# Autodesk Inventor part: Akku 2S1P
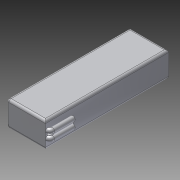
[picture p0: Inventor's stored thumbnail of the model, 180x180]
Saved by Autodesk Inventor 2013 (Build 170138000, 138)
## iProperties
Created: 2012-08
Part Number: Akku 2S1P
Material: LCP-Kunststoff
Document SubType Name: Modeling
Designer: rYan
Mass: 131.468 g
Surface Area: 137.12 cm^2
Volume: 80.8535 cm^3
Density: 1.626 g/cm^3
Author: rYan
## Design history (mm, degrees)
sketch "Skizze1"
  geometry: L1 (-17, 54)-(17, 54); L2 (17, 54)-(17, -54); L3 (17, -54)-(-17, -54); L4 (-17, -54)-(-17, 54); L5 (0, 75.6)-(0, -75.6) reference; L6 (-23.8, 0)-(23.8, 0) reference; 1 further point
  constraints: 8 end point, 2 parallel, 1 horizontal, 1 perpendicular, 2 other
  dimensions: "d0" = 34 distance of L1.start L1.end; "d2" = 108 distance of L1.end L2.end
extrude "Extrusion1" new body sketch "Skizze1" distance "d3" = 22; taper "d4" = 0 deg
fillet "Rundung1" dims "d5" = 2
workplane "Arbeitsebene1"
sketch "Skizze2"
  geometry: L1 (-17, -54)-(-17, 54) reference; L2 (15, -54)-(-17, -54) reference; L3 (-19, -50)-(-17, -50); L4 (-19, -50)-(-19, -32); A1 r 2 centre (-17, -50) between (-19, -50) and (-17, -52); 1 further point
  constraints: 4 end point, 2 perpendicular, 2 point on circle, 2 point on line, 1 centre point, 1 coincident, 1 tangent
  dimensions: "d6" = 2 radius of A1; "d8" = 2 distance from line of A1.end L2; "d11" = 18 distance of L3.start L4.end
sketch "Skizze3"
  geometry: L1 (-9, 129.6)-(-9, -21.6) reference; C1 r 0.75 at (-9, 2); 2 further points
  constraints: 1 centre point, 1 coincident
  dimensions: "d9" = 1.5 diameter of C1
feature "Sweeping1" sketch "Skizze2", "Skizze3" dims "d12" = 0
workplane "Arbeitsebene2"
sketch "Skizze4"
  geometry: L1 (-17, -52.75)-(-17, -51.25) reference; L2 (-17, 54)-(-17, -54) reference; L3 (-17, -54)-(-17, 54) reference; L4 (-17, -54)-(15, -54) reference; L5 (15, -54)-(-17, -54) reference; L6 (-17, -50)-(-19, -50); L7 (-19, -50)-(-19, -32); A1 r 2 centre (-17, -50) between (-19, -50) and (-17, -52); 1 further point
  constraints: 4 end point, 2 point on circle, 2 point on line, 1 centre point, 1 perpendicular, 1 tangent
  dimensions: "d18" = 2 radius of A1; "d20" = 2 distance from line of A1.end L4; "d21" = 90 deg angle of L2 L6; "d22" = 18 distance of L6.end L7.end
sketch "Skizze5"
  geometry: C1 r 2 at (-6, 2); 2 further points
  constraints: 1 centre point, 1 coincident
  dimensions: "d23" = 4 diameter of C1
feature "Sweeping2" sketch "Skizze4", "Skizze5" dims "d25" = 0
mirror "Spiegeln1"
node "Volumenkörper1"
node "Projizierte Kontur1"
node "Projizierte Kontur2"
other parameters: "d16" = 3
